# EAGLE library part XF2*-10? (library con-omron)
OMRON FPC Connector Source : http://www.omron.com/ecb/products/pdf/fpc.pdf
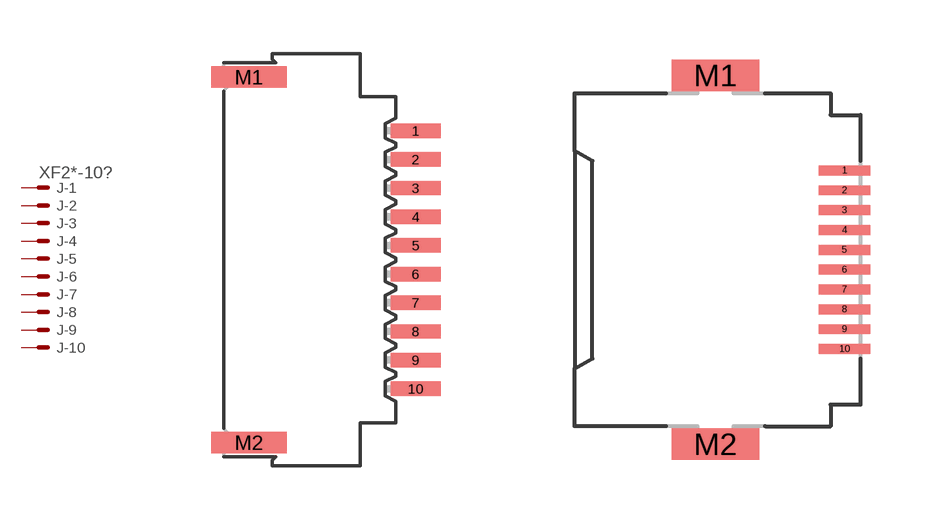
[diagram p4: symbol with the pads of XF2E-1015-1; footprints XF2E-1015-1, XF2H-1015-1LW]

Designator prefix J; gates -1=PV -2=P -3=P -4=P -5=P -6=P -7=P -8=P -9=P -10=P

## XF2E-1015-1 (MPN: XF2E-1015-1; OC_FARNELL: unknown; OC_NEWARK: 37M0755)  [XF2E-1015-1]
1  -1:MSV  pas
2  -2:MS  pas
3  -3:MS  pas
4  -4:MS  pas
5  -5:MS  pas
6  -6:MS  pas
7  -7:MS  pas
8  -8:MS  pas
9  -9:MS  pas
10  -10:MS  pas

## XF2H-1015-1LW (MPN: XF2H-1015-1LW; OC_FARNELL: unknown; OC_NEWARK: 12J5134)  [XF2H-1015-1LW]
Pads as for XF2E-1015-1

## XF2J-1024-11 (MF: OMRON COMPONENTS USA; MPN: XF2J-1024-11; OC_FARNELL: 1207843; OC_NEWARK: 29C7824)  [XF2J-1024-11]
Pads as for XF2E-1015-1

## XF2J-1024-12 (OC_FARNELL: unknown; OC_NEWARK: unknown)  [XF2J-1024-12]
Pads as for XF2E-1015-1

## XF2L-1025-1 (MPN: XF2L-1025-1; OC_FARNELL: unknown; OC_NEWARK: 37M0877)  [XF2L-1025-1]
Pads as for XF2E-1015-1

## XF2L-1035-1 (MPN: XF2L-1035-1A; OC_FARNELL: 1430928; OC_NEWARK: 59M3516)  [XF2L-1035-1]
Pads as for XF2E-1015-1

## Footprint XF2E-1015-1 (pad centres in mm)
Non-ZIF Type (0.8 mm-pitch) Source : http://www.omron.com/ecb/products/pdf/fpc.pdf
smd 1.4 x 0.4: 1 2.54,3.6; 2 2.54,2.8; 3 2.54,2; 4 2.54,1.2; 5 2.54,0.4; 6 2.54,-0.4; 7 2.54,-1.2; 8 2.54,-2; 9 2.54,-2.8; 10 2.54,-3.6
smd 2.1 x 0.6: M1 -2.11,5.1; M2 -2.11,-5.1

## Footprint XF2H-1015-1LW (pad centres in mm)
Standard Rotary Backlock Type (0.5 mm-pitch) Source : http://www.omron.com/ecb/products/pdf/fpc.pdf
smd 1.3 x 0.25: 1 3.175,2.25; 2 3.175,1.75; 3 3.175,1.25; 4 3.175,0.75; 5 3.175,0.25; 6 3.175,-0.25; 7 3.175,-0.75; 8 3.175,-1.25; 9 3.175,-1.75; 10 3.175,-2.25
smd 2.2 x 0.8: M1 -0.075,4.65; M2 -0.075,-4.65

## Footprint XF2J-1024-11 (pad centres in mm)
ZIF Slide-locking Type (0.5 mm-pitch) Standard Source : http://www.omron.com/ecb/products/pdf/fpc.pdf
smd 1.6 x 0.5: 1 1.2,2.25; 2 -1.2,1.75; 3 1.2,1.25; 4 -1.2,0.75; 5 1.2,0.25; 6 -1.2,-0.25; 7 1.2,-0.75; 8 -1.2,-1.25; 9 1.2,-1.75; 10 -1.2,-2.25
smd 2.9 x 1.4: M1 0,3.95; M2 0,-3.95

## Footprint XF2J-1024-12 (pad centres in mm)
ZIF Slide-locking Type (0.5 mm-pitch) Reverse Source : http://www.omron.com/ecb/products/pdf/fpc.pdf
smd 1.6 x 0.5: 1 -1.2,2.25; 2 1.2,1.75; 3 -1.2,1.25; 4 1.2,0.75; 5 -1.2,0.25; 6 1.2,-0.25; 7 -1.2,-0.75; 8 1.2,-1.25; 9 -1.2,-1.75; 10 1.2,-2.25
smd 2.9 x 1.4: M1 0,3.95; M2 0,-3.95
